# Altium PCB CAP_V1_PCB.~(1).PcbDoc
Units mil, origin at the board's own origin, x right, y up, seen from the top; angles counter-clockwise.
Board outline 2875.48 x 1261.06 mil, 2 copper layers (Top Layer, Bottom Layer); 38 components, 28 nets, 134 pads, 51 vias.
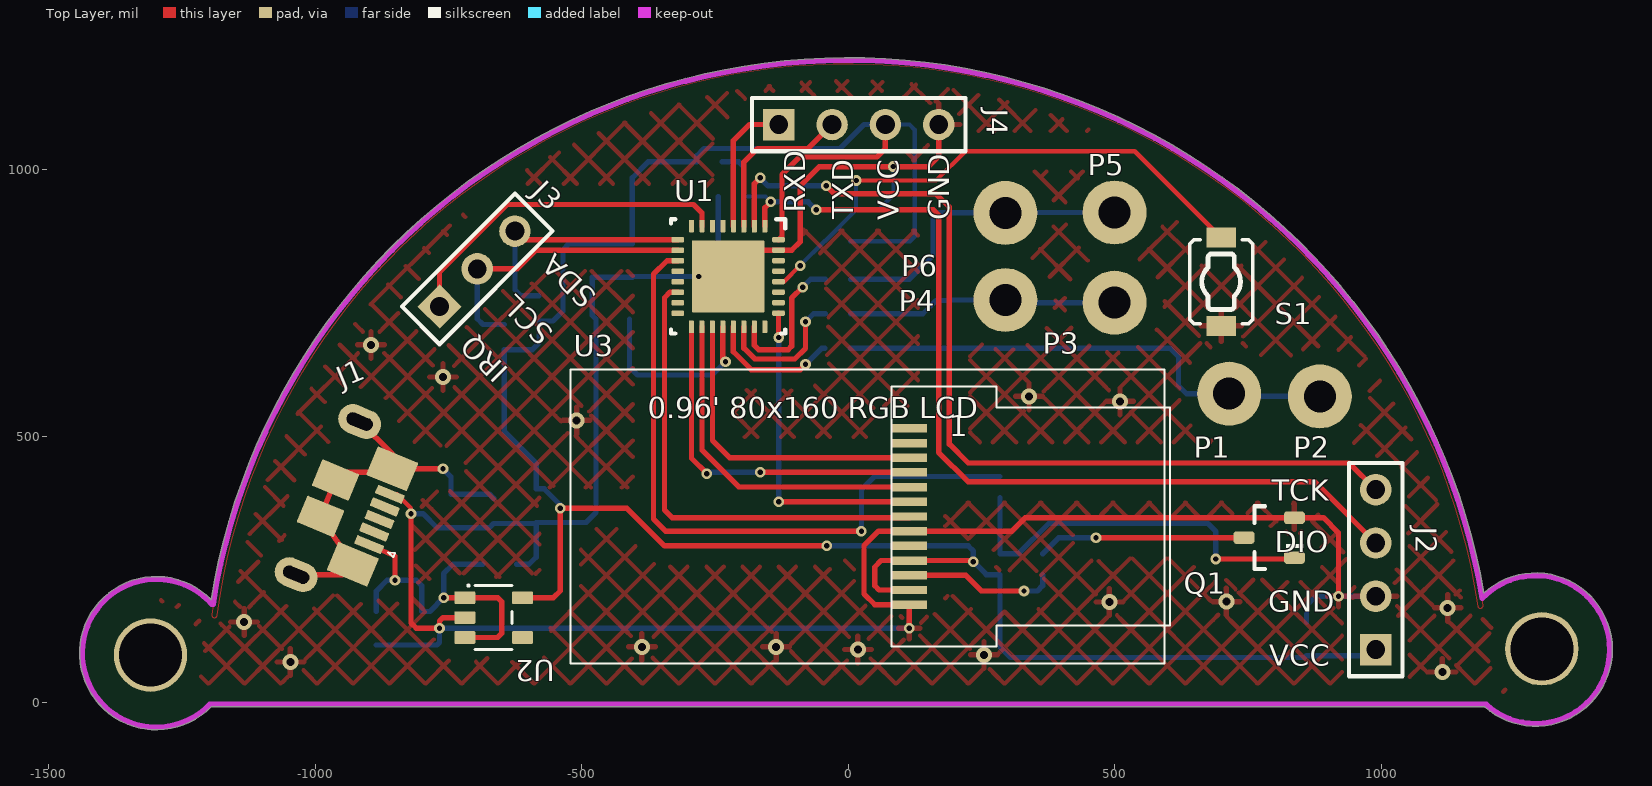
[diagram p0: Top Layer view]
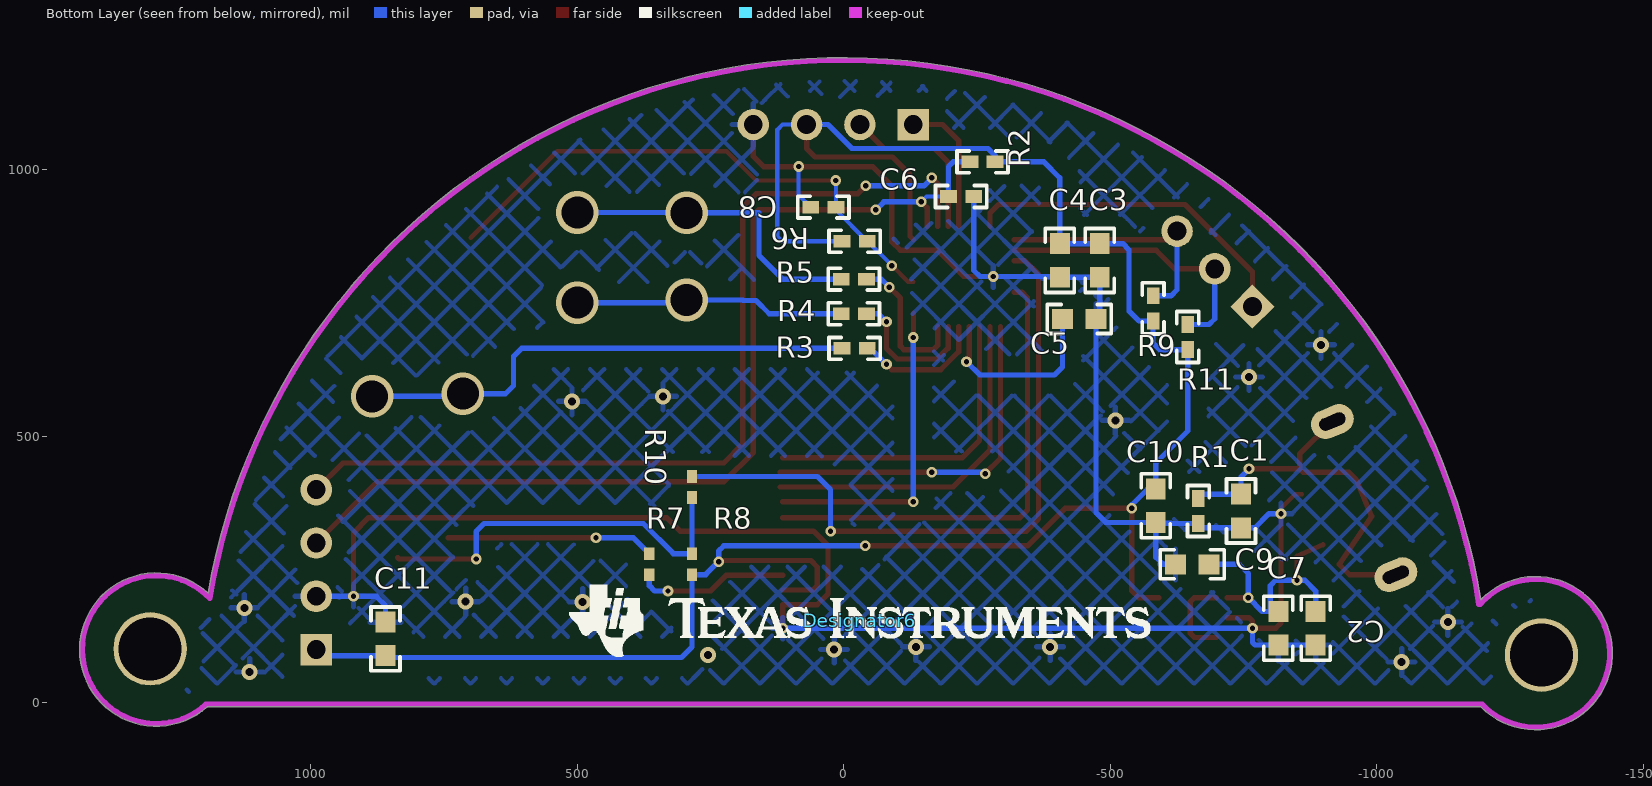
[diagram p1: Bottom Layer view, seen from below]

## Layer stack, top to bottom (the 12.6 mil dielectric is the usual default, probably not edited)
Top Solder: solder mask 0.4, Solder Resist, Dk 3.5
Top Layer: signal copper 1.4
Dielectric 1: dielectric 12.6, FR-4, Dk 4.8
Bottom Layer: signal copper 1.4
Bottom Solder: solder mask 0.4, Solder Resist, Dk 3.5

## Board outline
-1195.22,-7.54 cw(c-1297.84,93.22) -1194.92,193.67 cw(c0,0) 1192.85,206.04 cw(c1290,100) 1433.82,100 cw(c1290,100) 1194.51,-7.54

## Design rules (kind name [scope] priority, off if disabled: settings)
Clearance Ploygon [InPolygon] p1: gap=30 ignorepadtopadclearanceinfootprint=FALSE
Clearance [All] p2: gap=6 ignorepadtopadclearanceinfootprint=FALSE
PolygonConnect [All] p1: connectstyle=Relief reliefconductorwidth=10 reliefentries=4 polygonreliefangle="90 Angle" airgapwidth=10
RoutingVias [All] p1: holewidth=28 width=50 viastyle="Through Hole" minholewidth=10 minwidth=10 maxholewidth=28 maxwidth=100
SolderMaskExpansion [All] p1: expansion=4
Width [All] p1: maxlimit=10 minlimit=8 preferedwidth=8 minimp=50.000000 maximp=50.000000 favimp=50.000000
30 further rules are at their usual default settings.

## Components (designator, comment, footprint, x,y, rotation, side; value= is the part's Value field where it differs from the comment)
C1 "CGB3B1X5R1A475K055AC" 0603 -745,360 r270 bottom value=4.7uF
C2 "CGB3B1X5R1A475K055AC" 0603 -885,140 r270 bottom value=4.7uF
C3 "CGB3B1X5R1A475K055AC" 0603 -480,830 r270 bottom value=4.7uF
C4 "CGB3B1X5R1A475K055AC" 0603 -405,830 r270 bottom value=4.7uF
C5 "C1608X5R1A105K080AC" 0603 -441.5,720 r180 bottom value=1uF
C6 "GRM155R61H102KA01D" 0402 -220,950 r180 bottom value=1000pF
C7 "CGB3B1X5R1A475K055AC" 0603 -815,140 r270 bottom value=4.7uF
C8 "GRM155R61H102KA01D" 0402 38.62,930 r0 bottom value=1000pF
C9 "CGB3B1X5R1A475K055AC" 0603 -653.5,260 r0 bottom value=4.7uF
C10 "CGB3B1X5R1A475K055AC" 0603 -585,370 r270 bottom value=4.7uF
C11 "CGB3B1X5R1A475K055AC" 0603 860,120 r90 bottom value=4.7uF
Designator6 "Comment" TI_Horizontal_Overlay_Small -29.56,155 r180 bottom
J1 "1051640001" Molex_1051640001 -1028.62,405.95 r247.5 top
J2 "CONNECT 4P" HDR1X4 990,100 r90 top
J3 "CONNECT 3P" HDR1X3 -766.42,743.58 r45 top
J4 "CONNECT_4P" HDR1X4 -130,1085 r0 top
P1 "CAP" PCBComponent_1#1 715,580 r0 top
P2 "CAP" PCBComponent_1#1 885,575 r0 top
P3 "CAP" PCBComponent_1#1 500,750.79 r0 top
P4 "CAP" PCBComponent_1#2 295,755.79 r0 top
P5 "CAP" PCBComponent_1#1 500,920 r0 top
P6 "CAP" PCBComponent_1#1 295,919.21 r0 top
Q1 "S8050" SOT-23 790,310 r180 top value="30 V"
R1 "CRCW040247K0JNED" 0402 -665,360 r90 bottom value=47k
R2 "CRCW040247K0JNED" 0402 -260,1015 r180 bottom value=47k
R3 "CRCW040247K0JNED" 0402 -20,665 r180 bottom value=47k
R4 "CRCW040247K0JNED" 0402 -18.62,730 r180 bottom value=47k
R5 "CRCW040247K0JNED" 0402 -18.62,795 r180 bottom value=47k
R6 "CRCW040247K0JNED" 0402 -20,865.94 r0 bottom value=47k
R7 "CRCW040210R0JNED" 0402L 365,260 r270 bottom value=10
R8 "CRCW040210K0JNED" 0402L 285,260.32 r270 bottom value=10k
R9 "CRCW04024K70JNED" 0402 -580,740 r90 bottom value=4.7k
R10 "CRCW04021K00JNED" 0402L 285,405 r270 bottom value=1.0k
R11 "CRCW04024K70JNED" 0402 -645,686.38 r90 bottom value=4.7k
S1 "TL1015AF160QG" SW_TL1015AF160QG 700,790 r90 top
U1 "MSP430FR2533IRHBR" RHB0032E_NV -225,800 r270 top
U2 "TLV70033DDCT" DDC0005A_N -665,160 r0 top
U3 "0.96 inch LCD RGB display" GMT096-01 -520.83,74.06 r0 top

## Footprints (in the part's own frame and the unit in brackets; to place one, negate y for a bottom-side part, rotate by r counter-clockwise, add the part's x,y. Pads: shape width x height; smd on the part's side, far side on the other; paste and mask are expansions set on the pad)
0402 [mm] "0402 from SM-752 data"
  rect 0.8x0.6 smd: 1(-0.6,0) 2(0.6,0)
  silkscreen extent -1.22,-0.52 1.22,0.52, body extent -0.55,-0.3 0.55,0.3, height 0.6
0402L [mm] "0402 from SM-752 data"
  rect 0.6x0.5 smd: 1(-0.5,0) 2(0.5,0)
  body extent -0.55,-0.3 0.55,0.3, height 0.6
0603 [mm] "0603 from SM-752 data"
  rect 1x0.95 smd: 1(-0.8,0) 2(0.8,0)
  silkscreen extent -1.52,-0.69 1.52,0.69, body extent -0.87,-0.47 0.87,0.47, height 1
DDC0005A_N [mm]
  rrect17% 1x0.6 smd: 1(-1.375,0.95) 2(-1.375,0) 3(-1.375,-0.95) 4(1.375,-0.95) 5(1.375,0.95)
  silkscreen extent -1.25,-1.52 0.88,1.57, body extent -1.41,-1.45 1.41,1.45, height 1.1
GMT096-01 [mm]
  rect 1.7x0.4 smd: 1(16.15,11.2) 2(16.15,10.5) 3(16.15,9.8) 4(16.15,9.1) 5(16.15,8.4) 6(16.15,7.7) 7(16.15,7) 8(16.15,6.3) 9(16.15,5.6) 10(16.15,4.9) 11(16.15,4.2) 12(16.15,3.5) 13(16.15,2.8)
  silkscreen extent 0,0 28.57,14
HDR1X3 [mm] "Connector; Header; 3 Position"
  rect 1.5x1.5 hole 0.9: 1(0,0)
  round 1.5 hole 0.9: 2(2.54,0) 3(5.08,0)
  silkscreen extent -1.27,-1.27 6.35,1.27
HDR1X4 [mm] "Connector; Header; 4 Position"
  rect 1.5x1.5 hole 0.9: 1(0,0)
  round 1.5 hole 0.9: 2(2.54,0) 3(5.08,0) 4(7.62,0)
  silkscreen extent -1.27,-1.27 8.89,1.27
Molex_1051640001 [mm] "Receptacle, USB 2.0, Micro B, 5 Pos, 0.65mm Pitch, R/A, SMT"
  rrect22% 0.45x1.38 smd: 1(1.3,4.11) 2(0.65,4.11) 3(0,4.11) 4(-0.65,4.11) 5(-1.3,4.11)
  rrect7% 1.475x2.1 smd: 6(-2.463,3.75) 11(2.463,3.75)
  rrect100% 1.4x2.1 hole 0.6 slot 1.3 at 90 deg: 7(-3.95,1.45) 10(3.95,1.45)
  rrect7% 1.375x1.9 smd: 8(-0.938,1.45) 9(0.937,1.45)
  silkscreen extent 1.2,5.1 1.4,5.4, body extent -4.1,-0.7 4.1,4.47, height 2.45
PCBComponent_1#1 [mil]
  round 120 smd: 1(0,0)
  Bottom Layer lines w10: -70,0 0,0
PCBComponent_1#2 [mil]
  round 120 smd: 1(0,0)
  Bottom Layer lines w10: -70,0 -65,0 0,0
RHB0032E_NV [mm] "QFN, 32-Leads, Body 5x5mm, Pitch 0.5mm, Thermal Pad 3.45x3.45mm, TI Recommended"
  rrect40% 0.6x0.25 smd: 1(-2.4,1.75) 2(-2.4,1.25) 3(-2.4,0.75) 4(-2.4,0.25) 5(-2.4,-0.25) 6(-2.4,-0.75) 7(-2.4,-1.25) 8(-2.4,-1.75) 17(2.4,-1.75) 18(2.4,-1.25) 19(2.4,-0.75) 20(2.4,-0.25) 21(2.4,0.25) 22(2.4,0.75) 23(2.4,1.25) 24(2.4,1.75)
  rrect40% 0.25x0.6 smd: 9(-1.75,-2.4) 10(-1.25,-2.4) 11(-0.75,-2.4) 12(-0.25,-2.4) 13(0.25,-2.4) 14(0.75,-2.4) 15(1.25,-2.4) 16(1.75,-2.4) 25(1.75,2.4) 26(1.25,2.4) 27(0.75,2.4) 28(0.25,2.4) 29(-0.25,2.4) 30(-0.75,2.4) 31(-1.25,2.4) 32(-1.75,2.4)
  rrect3% 3.45x3.45 smd paste-1.725: 33(0,0)
  rrect7% 1.49x1.49 on Top Paste: ""(-0.845,0.845) ""(-0.845,-0.845) ""(0.845,0.845) ""(0.845,-0.845)
  silkscreen extent -2.72,-2.73 2.72,2.73, body extent -2.57,-2.57 2.58,2.58, height 1.01
SOT-23 [mm] "SOT23, 3-Leads, Body 2.9x1.3mm, Pitch 0.95mm, Lead Span 2.5mm, IPC Medium Density"
  rrect50% 1x0.6 smd: 1(-1.2,0.95) 2(-1.2,-0.95) 3(1.2,0)
  silkscreen extent -1.62,-1.5 0.7,1.5, body extent -1.16,-1.45 1.21,1.45, height 1
SW_TL1015AF160QG [mm] "E-Switch"
  rect 0.95x1.4 smd: 1(-2.1,0) 2(2.1,0)
  silkscreen extent -2,-1.5 2,1.5, body extent -2.3,-1.5 2.3,1.5, height 2
TI_Horizontal_Overlay_Small [mil]
  silkscreen extent -545,-68 545,67

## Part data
C1 C2 C9 C10 C11: library part CMP-0007105-2, "CAP, CERM, 4.7 uF, 10 V, +/- 10%, X5R, 0603", Cap_Case=0603, Manufacturer=TDK, Supplier Part Number 1=445-7482-1-ND, TempCo=X5R, Tolerance_%=10%, Value1=Unknown, Value2=10V, ValueDisplayed=1uF
C3: library part CMP-0007105-2, "CAP, CERM, 4.7 uF, 10 V, +/- 10%, X5R, 0603", Cap_Case=0603, Manufacturer=TDK, Supplier Part Number 1=445-7482-1-ND, TempCo=X5R, Tolerance_%=10%, Value1=Unknown, Value2=10V, ValueDisplayed=0.1uF
C4 C7: library part CMP-0007105-2, "CAP, CERM, 4.7 uF, 10 V, +/- 10%, X5R, 0603", Cap_Case=0603, Manufacturer=TDK, Supplier Part Number 1=445-7482-1-ND, TempCo=X5R, Tolerance_%=10%, Value1=Unknown, Value2=10V, ValueDisplayed=4.7uF
C5: library part CMP-0007002-5, "CAP, CERM, 1 uF, 10 V, +/- 10%, X5R, 0603", Cap_Case=0603, Manufacturer=TDK, Supplier Part Number 1=445-1321-1-ND, TempCo=X5R, Tolerance_%=10%, Value1=Unknown, Value2=10V, ValueDisplayed=1uF
C6 C8: library part CMP-0006613-2, "CAP, CERM, 1000 pF, 50 V, +/- 10%, X5R, 0402", Cap_Case=0402, Manufacturer=MuRata, Supplier Part Number 1=GRM155R61H102KA01D-ND, TempCo=X5R, Tolerance_%=10%, Value1=Unknown, Value2=50V, ValueDisplayed=1000pF
J1: library part CMP-0055311-1, "Receptacle, USB 2.0, Micro B, 5 Position, R/A, SMT", Color=Black, Current_A=1.8A, Manufacturer=Molex, Supplier Part Number 1=WM11263CT-ND, Voltage_V=30V
J4: library part "Header 4", "Header, 4-Pin"
Q1: library part CMP-0000378-2, "Transistor, NPN, 30 V, 0.1 A, SOT-23", Manufacturer="ON Semiconductor", PartNumber=BC849CLT1G, Supplier Part Number 1=BC849CLT1GOSCT-ND, Value1="0.1 A", Value2=800
R1: library part CMP-0026935-3, "RES, 47 k, 5%, 0.063 W, AEC-Q200 Grade 0, 0402", Manufacturer=Vishay-Dale, Power_W=63mW, Supplier Part Number 1=541-47KJCT-ND, TempCo="200 ppm/C", Tolerance_%=5%, Value2=0.063W, Value_Code=47k0, ValueDisplayed=33k
R2 R6: library part CMP-0026935-3, "RES, 47 k, 5%, 0.063 W, AEC-Q200 Grade 0, 0402", Manufacturer=Vishay-Dale, Power_W=63mW, Supplier Part Number 1=541-47KJCT-ND, TempCo="200 ppm/C", Tolerance_%=5%, Value2=0.063W, Value_Code=47k0, ValueDisplayed=47k
R3 R4 R5: library part CMP-0026935-3, "RES, 47 k, 5%, 0.063 W, AEC-Q200 Grade 0, 0402", Manufacturer=Vishay-Dale, Power_W=63mW, Supplier Part Number 1=541-47KJCT-ND, TempCo="200 ppm/C", Tolerance_%=5%, Value2=0.063W, Value_Code=47k0, ValueDisplayed=470
R7: library part CMP-0026827-3, "RES, 10, 5%, 0.063 W, AEC-Q200 Grade 0, 0402", Manufacturer=Vishay-Dale, Power_W=63mW, Supplier Part Number 1=541-10JCT-ND, TempCo="200 ppm/C", Tolerance_%=5%, Value2=0.063W, Value_Code=10R0, ValueDisplayed=10
R8: library part CMP-0026825-5, "RES, 10 k, 5%, 0.063 W, AEC-Q200 Grade 0, 0402", Manufacturer=Vishay-Dale, Power_W=63mW, Supplier Part Number 1=541-10KJCT-ND, TempCo="200 ppm/C", Tolerance_%=5%, Value2=0.063W, Value_Code=10k0, ValueDisplayed=10k
R9 R11: library part CMP-0026938-5, "RES, 4.7 k, 5%, 0.063 W, AEC-Q200 Grade 0, 0402", Manufacturer=Vishay-Dale, Power_W=63mW, Supplier Part Number 1=541-4.7KJCT-ND, TempCo="200 ppm/C", Tolerance_%=5%, Value2=0.063W, Value_Code=4k70, ValueDisplayed=4.7k
R10: library part CMP-0026852-3, "RES, 1.0 k, 5%, 0.063 W, AEC-Q200 Grade 0, 0402", Manufacturer=Vishay-Dale, Power_W=63mW, Supplier Part Number 1=541-1.0KJCT-ND, TempCo="200 ppm/C", Tolerance_%=5%, Value2=0.063W, Value_Code=1k00, ValueDisplayed=1.0k
S1: library part CMP-0002143-2, "Switch, Tactile, SPST-NO, 0.05A, 12V, SMT", CurrentRating_mA=50A, Manufacturer=E-Switch, Supplier Part Number 1=EG4344CT-ND
U1: library part CMP-0076461-1, "16 MHz Ultra-Low-Power Microcontroller with 16 KB FRAM, CapTIvate touch technology, RHB0032E (VQFN-32)", Alternate Manufacturer="Texas Instruments", Alternate PartNumber=MSP430FR2533IRHBT
U2: library part CMP-0035824-1, "Single Output LDO, 200 mA, Fixed 3.3 V Output, 2 to 5.5 V Input, with Low IQ, 5-pin SOT (DDC), -40 to 125 degC, Green (RoHS & no Sb/Br)", Manufacturer="Texas Instruments"
U3: library part GMT096-01

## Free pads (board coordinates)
  round 137.8 hole 118.11: 0(-1308.75,89.76) 1(1301.53,101.5)

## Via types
v1: diameter 20, hole 10, Top Layer to Bottom Layer, 30 vias
v2: diameter 30, hole 15, Top Layer to Bottom Layer, 15 vias
v3: diameter 80, hole 60, Top Layer to Bottom Layer, 6 vias

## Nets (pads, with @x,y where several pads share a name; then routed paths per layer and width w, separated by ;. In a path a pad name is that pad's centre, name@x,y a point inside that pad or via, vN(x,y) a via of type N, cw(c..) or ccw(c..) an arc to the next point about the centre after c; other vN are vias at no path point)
"5V USB": C2.1 C7.1 C9.1 J1.1 U2.1 U2.3 | length 665
  Top Layer w10: J1.1 -850,275 v1(-850,230) ; v1(-758.7,197.4) U2.1 ; -699.13,122.6 -657.4,122.6 -650,130 -650,190 -657.4,197.4 -699.13,197.4
  Bottom Layer w10: C2.1 -885,210 -865,230 v1(-850,230) -810,230 -800,220 -800,171.5 -784.61,171.5 v1(-758.7,197.4) -758.7,242.8 -741.5,260 C9.1
GND: C1.2 C2.2 C3.2 C4.2 C5.2 C6.2 C7.2 C8.2 C9.2 C10.2 C11.2 J1.5 J2.2 J4.4 Q1.2 R1.1 S1.1 U1.31 U1.33 U2.2 U3.8 U3.13 | length 4906.8
  Top Layer w8: J1.5 -846.31,391.31 -820,365 v1(-820,355)
  Top Layer w10: v1(-820,355) -820,150 -810,140 v1(-766.42,140) -766.42,153.58 -760,160 U2.2 ; v1(-280,800) U1.33 -175.79,849.21 U1.31 -105.79,849.21 -90,865 -90,970 -54,1006 151,1006 170,1025 J4.4 ; v1(115,140) U3.13 50,184.29 30,204.29 30,295 57.2,322.2 307.44,322.2 332.64,347.4 Q1.2 891.62,347.4 920,319.02 v1(920,200)
  Bottom Layer w8: C8.2 85,952.76 v1(85,1006.38)
  Bottom Layer w10: C2.2 C7.2 -771.5,108.5 -766.42,113.58 v1(-766.42,140) v1(115,140) ; v1(-820,355) -797.6,355 -771.1,328.5 C1.2 -672.87,328.5 R1.1 -587.13,336.38 C10.2 ; C9.2 -598.5,260 -585,273.5 C10.2 ; C6.2 -243.62,811.38 -255,800 v1(-280,800) -403.5,800 C4.2 C3.2 -480,727.01 C5.2 -472.99,357.01 -491.5,338.5 C10.2 ; C11.2 860,182.4 877.6,200 J2.2
  other v2: 1115,57.81 -1046.33,76.79 255,90 18.31,100 -386.85,105 -135,105 -1132.91,151.79 1125,178.19 490,189.41 709.48,190 -509.14,530 510,565.8 339.43,575 -760,611.45 -895,671.79
I2C_IRQ: J3.1 U1.7 | length 640.8
  Top Layer w10: J3.1 -766.42,808.58 -640,935 -290,935 -274.21,919.21 U1.7
I2C_SCL: J3.2 R11.2 U1.10 | length 539.4
  Top Layer w10: J3.2 -620.71,814.29 -585.79,849.21 U1.10
  Bottom Layer w10: J3.2 -695.71,720.71 -685,710 R11.2
I2C_SDA: J3.3 R9.2 U1.9 | length 471.9
  Top Layer w10: J3.3 -608.9,868.9 U1.9
  Bottom Layer w10: J3.3 -625,775 -613.62,763.62 R9.2
LCD_BLK: R10.1 U1.11 | length 1262.7
  Top Layer w10: U1.11 -339.76,829.53 -365,804.29 -365,345 -342.2,322.2 v1(25,322.2)
  Bottom Layer w10: v1(25,322.2) 25,400 49.69,424.68 R10.1
LCD_CS: U1.14 U3.7 | length 893
  Top Layer w10: U1.14 -334.06,770.47 -344.53,760 -344.53,361.93 -330,347.4 U3.7@115,347.4
LCD_DC: U1.18 U3.5 | length 654.2
  Top Layer w10: U1.18 -274.21,474.21 -204.88,404.88 U3.5@120,404.88
LCD_RES: U1.25 U3.6 | length 599.1
  Top Layer w10: U1.25 -130.51,685.98 v1(-130,685.47) ; v1@-129.92,377.32 v1(-130,377.4) 114.8,377.4 U3.6
  Bottom Layer w10: v1(-130,377.4) v1(-130,685.47)
LCD_SCL: U1.17 U3.4 | length 673.5
  Top Layer w10: U1.17 -293.9,458.9 v1(-265,430) ; v1(-165,432.44) U3.4@120,432.44
  Bottom Layer w10: v1(-265,430) -262.56,432.44 v1(-165,432.44)
LCD_SDA: U1.19 U3.3 | length 596.2
  Top Layer w10: U1.19 -254.53,492.09 -222.44,460 U3.3@115,460
LEDK: R7.2 U3.11 | length 286.7
  Top Layer w10: U3.11@115,239.53 220.47,239.53 250,210 v1(330,210)
  Bottom Layer w10: v1(330,210) 355,210 365,220 R7.2
NetC1_1: C1.1 J1.6 J1.7 J1.8 J1.9 J1.10 J1.11 R1.2 | length 758.1
  Top Layer w10: J1.10 -948.77,240.43 J1.11 J1.9 J1.8 -947.51,432.44 -861.69,432.44 J1.6 ; J1.7 -855.12,466.53 J1.6 ; v1(-760,439.02) J1.6
  Bottom Layer w10: v1(-760,439.02) -745,424.02 C1.1 -672.87,391.5 R1.2
NetC8_1: C8.1 R6.1 S1.2 U1.28 | length 1031.6
  Top Layer w8: U1.28 -120.22,790.16 v1(-90,820.37) ; v1(15,980) 165,980 220,1035 537.68,1035 S1.2
  Bottom Layer w8: v1(-90,820.37) -44.43,865.94 R6.1 15,924.57 C8.1 v1(15,980)
NetQ1_1: Q1.1 R8.1 R10.2 | length 739.6
  Top Layer w10: v1(690,270) 834.65,270 Q1.1
  Bottom Layer w10: R10.2 R8.1 320,280 376.38,336.38 675,336.38 690,321.38 v1(690,270)
NetQ1_3: Q1.3 R7.1 | length 390.3
  Top Layer w10: v1(465,310) Q1.3
  Bottom Layer w10: R7.1 395.31,310 v1(465,310)
NetR3_2: R3.2 U1.21 | length 248.8
  Top Layer w10: U1.21 -215.16,658.78 -181.38,625 -90,625 v1(-80,635)
  Bottom Layer w10: v1(-80,635) -50,665 R3.2
NetR4_2: R4.2 U1.22 | length 266.2
  Top Layer w10: U1.22 -195.47,665.47 -175,645 -100,645 -80,665 v1(-80,715)
  Bottom Layer w10: v1(-80,715) -65,730 R4.2
NetR5_2: R5.2 U1.23 | length 279.1
  Top Layer w10: U1.23 -175.79,670.79 -167.76,662.76 -112.24,662.76 -105.79,669.21 -105.79,759.21 v1(-85,780)
  Bottom Layer w10: v1(-85,780) -70,795 R5.2
SBWTCK_TEST: J2.4 U1.2 | length 1752.7
  Top Layer w10: U1.2 -175.79,974.21 v1(-165,985) ; v1(-40.79,970) -25.79,955 165,955 190,930 190,485.47 225.47,450 940,450 J2.4
  Bottom Layer w10: v1(-165,985) -150,970 v1(-40.79,970)
SBWTDIO_RST: C6.1 J2.3 R2.1 U1.1 | length 1866.4
  Top Layer w10: U1.1 -156.1,928.9 v1(-145,940) ; v1(-60,925) 160,925 170,915 170,470 225,415 875,415 J2.3
  Bottom Layer w8: C6.1 -155,950 v1(-145,940)
  Bottom Layer w10: R2.1 -205,1015 -196.38,1006.38 C6.1 ; v1(-145,940) -75,940 v1(-60,925)
TP1.0: P1.1 P2.1 R3.1 | length 810.9
  Bottom Layer w10: R3.1 605,665 620,650 620,595 635,580 645,580 ; v3(715,580) 720,575 815,575
  other v3: 885,575
TP1.1: P3.1 P4.1 R4.1 | length 372.8
  Bottom Layer w10: R4.1 140,730 165,755 189.21,755 190,755.79 230,755.79 ; v3(295,755.79) 300,750.79 430,750.79
  other v3: 500,750.79
TP1.2: P5.1 P6.1 R5.1 | length 453.6
  Bottom Layer w10: R5.1 115,795 159.21,839.21 159.21,919.21 225,919.21 ; v3(295,919.21) 295.79,920 430,920
  other v3: 500,920
UART0_RXD: J4.1 U1.4 | length 258
  Top Layer w10: U1.4 -215.16,1054.84 -185,1085 J4.1
UART0_TXD: J4.2 U1.3 | length 314.7
  Top Layer w10: U1.3 -195.47,1014.53 -170,1040 -75,1040 J4.2
VCC: C3.1 C4.1 C10.1 C11.1 J2.1 J4.3 R2.2 R6.2 R8.2 R9.1 R11.1 U1.32 U2.5 U3.10 U3.12 | length 4425.4
  Top Layer w10: -590.87,197.4 -552.6,197.4 -540,210 v1(-540,365) -415,365 -344.53,294.53 v1(-40,294.53) ; U1.32 -124,875.41 -124,991 -91,1024 54,1024 70,1040 J4.3 ; U3.12 58.15,211.85 50,220 50,255 61.97,266.97 U3.10 ; U3.10@117.21,267.09 232.91,267.09 v1(235,265)
  Bottom Layer w8: R6.2 115.94,865.94 125,875 125,1075 115,1085 J4.3
  Bottom Layer w10: v1(-540,365) -540,371.5 -570,401.5 C10.1 -585,450 -645,510 R11.1 -592.24,662.76 -580,675 R9.1 -553.62,716.38 -535,735 -535,850 -523.5,861.5 C3.1 C4.1 -405,985 -375,1015 R2.2 -283.62,1026.38 -270,1040 -15,1040 30,1085 J4.3 ; v1(-40,294.53) 225.47,294.53 235,285 v1(235,265) 259.37,240.63 R8.2 285,105 305,85 856.5,85 C11.1 978.5,88.5 J2.1
VREG: C5.1 U1.20 | length 354.1
  Top Layer w10: U1.20 -234.84,644.84 v1(-230,640)
  Bottom Layer w10: C5.1 -410,630 -395,615 -255,615 v1(-230,640)
pads on no net: J1.2 J1.3 J1.4 U1. U1.5 U1.6 U1.8 U1.12 U1.13 U1.15 U1.16 U1.24 U1.26 U1.27 U1.29 U1.30 U2.4 U3.1 U3.2 U3.9

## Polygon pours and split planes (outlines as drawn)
GND on Top Layer "Top Layer-No Net2" (hatched 45Degree grid 48 track 8, remove dead copper, pour order 34): -1195.22,-7.54 cw(c-1297.84,93.22) -1194.92,193.67 cw(c0,0) 1192.85,206.04 cw(c1290,100) 1433.82,100 cw(c1290,100) 1194.51,-7.54
no net on Top Layer "Top Layer-No Net1" (none, pour order 14): -1193.7,165.5 ccw(c-1188.73,164.83) -1183.76,164.16 cw(c0,5) 1181.28,181.62 ccw(c1186.24,182.36) 1191.26,182.36 ccw(c1186.24,182.36) 1191.2,183.1 ccw(c0,5)
no net on Top Layer "Top Layer-No Net 1" (none, pour order 8): -1193.7,165.5 ccw(c-1188.73,164.83) -1183.76,164.16 cw(c0,5) 1181.28,181.62 ccw(c1186.24,182.36) 1191.26,182.36 ccw(c1186.24,182.36) 1191.2,183.1 ccw(c0,5)
no net on Top Layer "Top Layer-No Net" (solid, pour order 6): 5895,1140
GND on Bottom Layer "Top Layer-No Net3" (hatched 45Degree grid 48 track 8, remove dead copper, pour order 33): -1195.22,-7.54 cw(c-1297.84,93.22) -1194.92,193.67 cw(c0,0) 1192.85,206.04 cw(c1290,100) 1433.82,100 cw(c1290,100) 1194.51,-7.54

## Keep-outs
Top Layer:
  lines w10: -4060,-2575 -4020,-2615 ; 8325,-2615 8330,-2620
Keep-Out Layer:
  lines w10: -1193.94,185.26 ccw(c-1297.84,93.22) -1197.34,-2.53 1197.53,-2.53 ; -1191.19,185.18 cw(c0,0) 1189.5,195.74 cw(c1290,100) 1197.78,-3.74

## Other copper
Top Layer:
  pour cut-out: 208.68,865.94 248.27,865.94 265,849.21 265,831.71 263.72,831.71 241.04,809.03 208.68,809.03
  pour cut-out: 720,501.19 773.81,555 803.56,555 803.56,547.37 870.93,480 861.27,470.34 725,470.34

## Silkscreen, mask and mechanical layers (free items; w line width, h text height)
Top Overlay:
  text "RXD" at -80,919.21 h40 r90
  text "TXD" at 10,907.28 h40 r90
  text "VCC" at 95,905 h40 r90
  text "GND" at 190,905 h40 r90
  text "SDA" at -470,765 h40 r135
  text "SCL" at -550,695 h40 r135
  text "IRQ" at -635,625 h40 r135
  text "1" at 190,500 h40
  text "TCK" at 795,378.87 h40
  text "DIO" at 800,282.44 h40
  text "GND" at 788.68,171 h40
  text "VCC" at 790,70 h40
